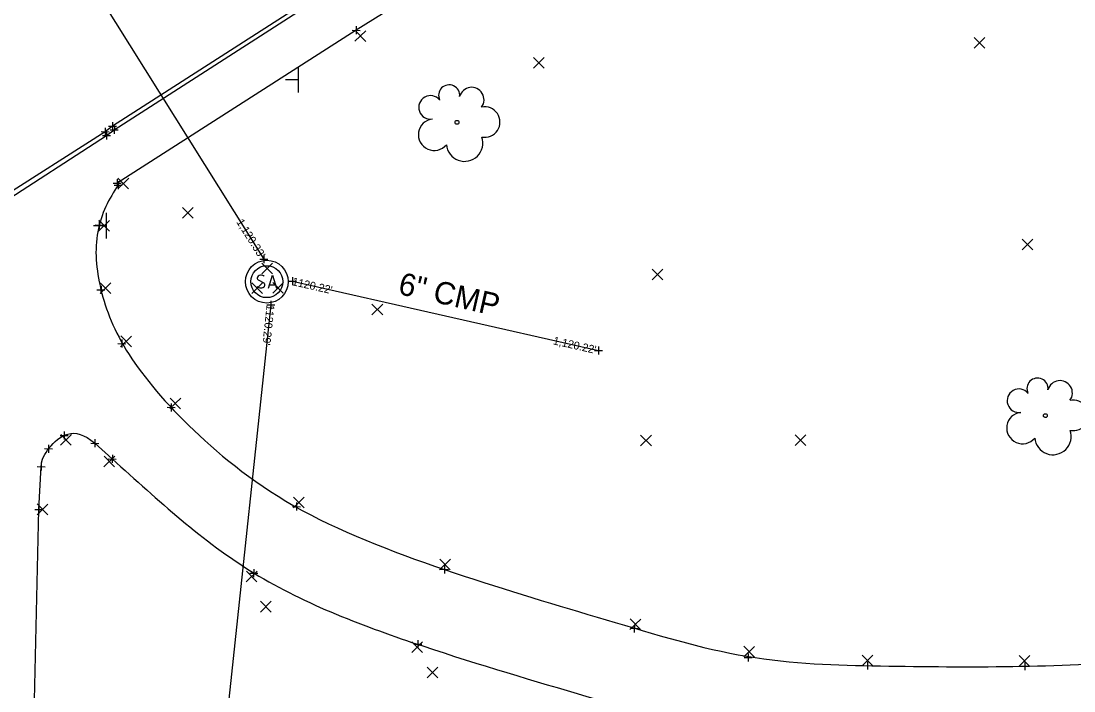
# Model space of a CAD drawing. Extents: x 142461 to 147261, y 511126 to 514697.
# Drawn here: x 145052.6 to 145184.1, y 512896.1 to 512979.9 of the extents above; entities that cross this region are included whole.
import ezdxf

# ---------------------------------------------------------------- set-up
doc = ezdxf.new("R2010")
doc.units = 0
for name, color, linetype in [('DR_X_Elev_Flow', 7, 'Continuous'), ('GK_Drainage_Nodes', 7, 'Continuous'), ('PV_X_Curb', 7, 'Continuous'), ('PV_X_EOP', 7, 'Continuous'), ('PV_X_Walk', 7, 'Continuous'), ('SC_Scratch1', 7, 'Continuous'), ('SN_X_Public', 7, 'Continuous'), ('SV_X_Random_Point', 7, 'Continuous'), ('SV_X_Shot_Marker', 7, 'Continuous'), ('UT_X_Sanitary_Cells', 7, 'Continuous'), ('UT_X_Sanitary_Line', 7, 'Continuous'), ('UT_X_Sanitary_Text', 7, 'Continuous'), ('VG_X_Cells', 7, 'Continuous')]:
    doc.layers.add(name, color=color, linetype=linetype)

msp = doc.modelspace()

# ---------------------------------------------------------------- linework, layer by layer
at = {"layer": 'DR_X_Elev_Flow'}
for p, q in [((145082.93, 512950.61), (145082.93, 512949.61)), ((145082.43, 512950.11), (145083.43, 512950.11)), ((145082.93, 512950.11), (145082.93, 512950.11)), ((145086.49, 512947.84), (145086.49, 512946.84)), ((145085.99, 512947.34), (145086.99, 512947.34)), ((145086.49, 512947.34), (145086.49, 512947.34)), ((145083.27, 512944.38), (145084.27, 512944.38)), ((145083.77, 512944.88), (145083.77, 512943.88)), ((145083.77, 512944.38), (145083.77, 512944.38)), ((145124.24, 512938.66), (145125.24, 512938.66)), ((145124.74, 512939.16), (145124.74, 512938.16)), ((145124.74, 512938.66), (145124.74, 512938.66))]:
    msp.add_line(p, q, dxfattribs=at)
at = {"layer": 'GK_Drainage_Nodes'}
for p, q in [((145083.28, 512949.28), (145083.28, 512949.28)), ((145083.28, 512947.28), (145083.28, 512947.28)), ((145083.28, 512947.28), (145083.28, 512947.28)), ((145083.28, 512947.28), (145083.28, 512947.28)), ((145083.28, 512945.28), (145083.28, 512945.28))]:
    msp.add_line(p, q, dxfattribs=at)
msp.add_circle((145083.28, 512947.28), 2, dxfattribs=at)
at = {"layer": 'PV_X_Curb'}
for p, q in [((145064.23, 512966.25), (145090.73, 512983.33)), ((145063.26, 512965.57), (145064.23, 512966.25)), ((145037.9, 512949.14), (145063.26, 512965.57))]:
    msp.add_line(p, q, dxfattribs=at)
at = {"layer": 'PV_X_EOP'}
for p, q in [((145090.36, 512983.65), (145064.01, 512966.73)), ((145064.01, 512966.73), (145063.08, 512966.03)), ((145063.08, 512966.03), (145037.41, 512949.6))]:
    msp.add_line(p, q, dxfattribs=at)
at = {"layer": 'PV_X_Walk'}
for p, q in [((145126.2, 512998.67), (145094.47, 512978.71)), ((145094.47, 512978.71), (145064.59, 512959.6)), ((145064.59, 512959.6), (145064.73, 512959.34)), ((145061.8, 512927.07), (145063.98, 512925.11)), ((145054.78, 512918.79), (145055.08, 512924.15)), ((145053.92, 512878.99), (145054.78, 512918.79))]:
    msp.add_line(p, q, dxfattribs=at)
for points in [[(145064.73, 512959.34), (145063.58, 512957.75), (145061.55, 512953.72), (145062.14, 512946.4), (145065.23, 512938.47), (145073.35, 512928.85), (145086.5, 512918.18), (145106.96, 512910.53), (145125.95, 512904.95), (145143.43, 512899.62), (145159.95, 512899.19), (145176.54, 512899.04), (145192.88, 512899.67), (145208.86, 512902.71), (145224.67, 512905.94), (145240.68, 512909.6), (145253.08, 512914.56), (145260.17, 512918.77), (145262.94, 512920.64)], [(145055.08, 512924.15), (145055.13, 512925.02), (145055.9, 512926.48), (145058.26, 512928.72), (145060.47, 512928.25), (145061.8, 512927.07)], [(145063.98, 512925.11), (145069.77, 512919.92), (145080.69, 512909.67), (145103.07, 512901.33), (145123.63, 512895.37), (145142.03, 512889.72), (145159.63, 512889.13), (145176.81, 512888.85), (145194, 512889.65), (145209.87, 512893.18), (145224.9, 512894.34), (145240.29, 512892.09), (145248.15, 512887), (145251.76, 512882.95)]]:
    msp.add_open_spline(points, degree=3, dxfattribs=at)
at = {"layer": 'SN_X_Public'}
for p, q in [((145087.22, 512974.13), (145087.22, 512970.93)), ((145087.22, 512972.53), (145085.62, 512972.53)), ((145087.22, 512972.53), (145087.22, 512972.53)), ((145063.23, 512955.87), (145063.23, 512952.67)), ((145063.23, 512954.27), (145061.63, 512954.27)), ((145063.23, 512954.27), (145063.23, 512954.27))]:
    msp.add_line(p, q, dxfattribs=at)
at = {"layer": 'SV_X_Random_Point'}
for p, q in [((145094.3, 512977.34), (145095.65, 512978.66)), ((145094.32, 512978.67), (145095.64, 512977.32)), ((145171.68, 512976.47), (145173.02, 512977.81)), ((145171.68, 512977.81), (145173.02, 512976.47)), ((145116.63, 512973.97), (145117.96, 512975.3)), ((145116.63, 512975.3), (145117.96, 512973.97)), ((145064.68, 512958.89), (145066.03, 512960.21)), ((145064.69, 512960.23), (145066.01, 512958.88)), ((145072.76, 512955.22), (145074.09, 512956.55)), ((145072.76, 512956.55), (145074.09, 512955.22)), ((145062.27, 512953.61), (145063.62, 512954.93)), ((145062.29, 512954.95), (145063.61, 512953.6)), ((145177.68, 512951.25), (145179.01, 512952.59)), ((145177.68, 512952.59), (145179.01, 512951.25)), ((145082.67, 512948.26), (145084.01, 512949.58)), ((145082.68, 512949.6), (145084, 512948.25)), ((145131.44, 512947.51), (145132.78, 512948.84)), ((145131.44, 512948.84), (145132.78, 512947.51)), ((145062.45, 512945.8), (145063.8, 512947.12)), ((145062.47, 512947.13), (145063.79, 512945.78)), ((145081.41, 512945.82), (145082.75, 512947.14)), ((145081.42, 512947.15), (145082.74, 512945.81)), ((145084.02, 512945.85), (145085.36, 512947.17)), ((145084.03, 512947.18), (145085.35, 512945.83)), ((145096.43, 512943.12), (145097.77, 512944.45)), ((145096.43, 512944.45), (145097.77, 512943.12)), ((145065.02, 512939.15), (145066.37, 512940.47)), ((145065.04, 512940.49), (145066.36, 512939.14)), ((145071.18, 512931.4), (145072.53, 512932.72)), ((145071.2, 512932.73), (145072.52, 512931.38)), ((145057.52, 512926.84), (145058.87, 512928.16)), ((145057.54, 512928.18), (145058.85, 512926.83)), ((145130, 512926.74), (145131.34, 512928.07)), ((145130, 512928.07), (145131.34, 512926.74)), ((145149.32, 512926.81), (145150.65, 512928.14)), ((145149.32, 512928.14), (145150.65, 512926.81)), ((145062.93, 512924.12), (145064.28, 512925.44)), ((145062.95, 512925.46), (145064.27, 512924.11)), ((145086.62, 512919.02), (145087.96, 512920.34)), ((145086.63, 512920.35), (145087.95, 512919)), ((145054.59, 512918.14), (145055.94, 512919.46)), ((145054.61, 512919.48), (145055.93, 512918.13)), ((145104.88, 512911.26), (145106.23, 512912.58)), ((145104.89, 512912.6), (145106.21, 512911.25)), ((145080.72, 512909.75), (145082.06, 512911.07)), ((145080.73, 512911.09), (145082.05, 512909.74)), ((145082.49, 512905.97), (145083.83, 512907.31)), ((145082.49, 512907.31), (145083.83, 512905.97)), ((145128.66, 512903.78), (145130.01, 512905.1)), ((145128.68, 512905.12), (145129.99, 512903.77)), ((145101.4, 512900.91), (145102.75, 512902.23)), ((145101.41, 512902.25), (145102.73, 512900.9)), ((145142.88, 512900.36), (145144.23, 512901.68)), ((145142.9, 512901.69), (145144.22, 512900.34)), ((145157.68, 512899.25), (145159.02, 512900.57)), ((145157.69, 512900.59), (145159.01, 512899.24)), ((145177.31, 512899.19), (145178.65, 512900.52)), ((145177.32, 512900.53), (145178.64, 512899.18)), ((145103.33, 512897.75), (145104.67, 512899.09)), ((145103.33, 512899.09), (145104.67, 512897.75))]:
    msp.add_line(p, q, dxfattribs=at)
at = {"layer": 'SV_X_Shot_Marker'}
for p, q in [((145093.97, 512978.71), (145094.97, 512978.7)), ((145094.47, 512979.21), (145094.46, 512978.21)), ((145094.47, 512978.71), (145094.47, 512978.71)), ((145063.08, 512966.53), (145063.07, 512965.53)), ((145063.51, 512966.73), (145064.51, 512966.72)), ((145063.73, 512966.26), (145064.73, 512966.25)), ((145064.02, 512967.23), (145064, 512966.23)), ((145064.01, 512966.73), (145064.01, 512966.73)), ((145064.24, 512966.75), (145064.23, 512965.75)), ((145064.23, 512966.25), (145064.23, 512966.25)), ((145062.58, 512966.04), (145063.58, 512966.03)), ((145062.76, 512965.57), (145063.76, 512965.56)), ((145063.08, 512966.03), (145063.08, 512966.03)), ((145063.26, 512966.07), (145063.25, 512965.07)), ((145063.26, 512965.57), (145063.26, 512965.57)), ((145064.09, 512959.61), (145065.09, 512959.6)), ((145064.6, 512960.1), (145064.59, 512959.1)), ((145064.59, 512959.6), (145064.59, 512959.6)), ((145064.73, 512959.84), (145064.72, 512958.84)), ((145064.23, 512959.34), (145065.23, 512959.33)), ((145064.73, 512959.34), (145064.73, 512959.34)), ((145061.83, 512954.37), (145062.83, 512954.36)), ((145062.34, 512954.86), (145062.33, 512953.86)), ((145062.33, 512954.36), (145062.33, 512954.36)), ((145062.57, 512946.74), (145062.56, 512945.74)), ((145062.06, 512946.25), (145063.06, 512946.24)), ((145062.56, 512946.24), (145062.56, 512946.24)), ((145065.17, 512940.03), (145065.16, 512939.03)), ((145064.67, 512939.53), (145065.67, 512939.52)), ((145065.17, 512939.53), (145065.17, 512939.53)), ((145071.34, 512932.06), (145071.33, 512931.06)), ((145070.84, 512931.57), (145071.84, 512931.56)), ((145071.34, 512931.56), (145071.34, 512931.56)), ((145057.47, 512928.05), (145058.47, 512928.04)), ((145057.97, 512928.55), (145057.96, 512927.55)), ((145057.97, 512928.05), (145057.97, 512928.05)), ((145056.01, 512926.89), (145056, 512925.89)), ((145061.3, 512927.07), (145062.3, 512927.06)), ((145061.8, 512927.57), (145061.79, 512926.57)), ((145061.8, 512927.07), (145061.8, 512927.07)), ((145055.51, 512926.4), (145056.51, 512926.39)), ((145056.01, 512926.39), (145056.01, 512926.39)), ((145063.99, 512925.61), (145063.98, 512924.61)), ((145054.58, 512924.15), (145055.58, 512924.14)), ((145055.09, 512924.65), (145055.08, 512923.65)), ((145055.08, 512924.15), (145055.08, 512924.15)), ((145063.48, 512925.11), (145064.48, 512925.1)), ((145063.98, 512925.11), (145063.98, 512925.11)), ((145054.28, 512918.8), (145055.28, 512918.79)), ((145054.79, 512919.29), (145054.78, 512918.29)), ((145054.78, 512918.79), (145054.78, 512918.79)), ((145086.5, 512919.15), (145087.5, 512919.14)), ((145087.01, 512919.65), (145087, 512918.65)), ((145087, 512919.15), (145087, 512919.15)), ((145081.65, 512911.34), (145081.64, 512910.34)), ((145104.99, 512911.32), (145105.99, 512911.31)), ((145105.49, 512911.81), (145105.48, 512910.81)), ((145105.49, 512911.31), (145105.49, 512911.31)), ((145081.15, 512910.84), (145082.15, 512910.83)), ((145081.65, 512910.84), (145081.65, 512910.84)), ((145129.22, 512904.43), (145129.21, 512903.43)), ((145128.72, 512903.94), (145129.72, 512903.93)), ((145129.22, 512903.93), (145129.22, 512903.93)), ((145101.66, 512901.95), (145102.66, 512901.94)), ((145102.17, 512902.44), (145102.16, 512901.44)), ((145102.16, 512901.94), (145102.16, 512901.94)), ((145143.45, 512900.79), (145143.44, 512899.79)), ((145142.95, 512900.3), (145143.95, 512900.29)), ((145143.45, 512900.29), (145143.45, 512900.29)), ((145157.86, 512899.27), (145158.86, 512899.26)), ((145158.36, 512899.76), (145158.35, 512898.77)), ((145158.36, 512899.26), (145158.36, 512899.26)), ((145177.49, 512899.2), (145178.49, 512899.19)), ((145178, 512899.7), (145177.99, 512898.7)), ((145177.99, 512899.2), (145177.99, 512899.2))]:
    msp.add_line(p, q, dxfattribs=at)
at = {"layer": 'UT_X_Sanitary_Cells'}
for points in [[(145082.95, 512947.96), (145082.93, 512947.99), (145082.89, 512948.01), (145082.77, 512948.05), (145082.64, 512948.08), (145082.53, 512948.08), (145082.5, 512948.08), (145082.33, 512948.04), (145082.19, 512947.96), (145082.11, 512947.86), (145082.08, 512947.76), (145082.08, 512947.69), (145082.11, 512947.59), (145082.21, 512947.5), (145082.9, 512947.12), (145082.96, 512947.07), (145082.99, 512947.02), (145083.01, 512946.94), (145083.01, 512946.87), (145083, 512946.79), (145082.99, 512946.74), (145082.96, 512946.68), (145082.94, 512946.63), (145082.91, 512946.59), (145082.87, 512946.55), (145082.84, 512946.53), (145082.79, 512946.5), (145082.75, 512946.49), (145082.64, 512946.48), (145082.46, 512946.48), (145082.35, 512946.5), (145082.18, 512946.59), (145082.08, 512946.67)], [(145083.49, 512946.48), (145084, 512948.08), (145084.49, 512946.48)], [(145084.36, 512946.86), (145083.62, 512946.86)]]:
    msp.add_lwpolyline(points, dxfattribs=at)
for radius in [2.67, 2]:
    msp.add_circle((145083.28, 512947.28), radius, dxfattribs=at)
at = {"layer": 'UT_X_Sanitary_Line'}
for p, q in [((144979.11, 513115.64), (145082.93, 512950.11)), ((145086.49, 512947.34), (145124.74, 512938.66)), ((145083.77, 512944.38), (145069.22, 512807.59))]:
    msp.add_line(p, q, dxfattribs=at)
at = {"layer": 'VG_X_Cells'}
for centre in [(145107.05, 512967.2), (145180.58, 512930.53)]:
    msp.add_circle(centre, 0.24, dxfattribs=at)
for centre, radius, start, end in [((145106.07, 512970.57), 1.32, 354.0047, 205.9741), ((145108.88, 512970.03), 1.55, 323.83, 165.0376), ((145103.74, 512969.07), 1.47, 39.0625, 279.5412), ((145110.51, 512967.24), 1.91, 259.1453, 101.4596), ((145104.2, 512965.65), 1.97, 96.1722, 320.5737), ((145108, 512964.6), 2.28, 184.9476, 19.4572), ((145179.59, 512933.9), 1.32, 354.0047, 205.9741), ((145182.4, 512933.36), 1.55, 323.83, 165.0376), ((145177.27, 512932.39), 1.47, 39.0625, 279.5412), ((145184.04, 512930.56), 1.91, 259.1453, 101.4596), ((145177.72, 512928.98), 1.97, 96.1722, 320.5737), ((145181.52, 512927.92), 2.28, 184.9476, 19.4572)]:
    msp.add_arc(centre, radius, start, end, dxfattribs=at)

# ---------------------------------------------------------------- texts
at = {"layer": 'SC_Scratch1'}
for s, rotation, p in [("1,120.33'", 302.0959, (145079.44, 512954.74)), ("1120.22'", 347.2201, (145086.38, 512946.85)), ("1120.29'", 263.9289, (145083.27, 512944.44)), ("1,120.22'", 347.2201, (145118.99, 512939.46))]:
    msp.add_text(s, height=1, rotation=rotation, dxfattribs=at).set_placement(p)
at = {"layer": 'UT_X_Sanitary_Text'}
msp.add_text('6" CMP', height=2.8, rotation=347.2201, dxfattribs=at).set_placement((145099.57, 512945.76))

doc.saveas('drawing.dxf')
